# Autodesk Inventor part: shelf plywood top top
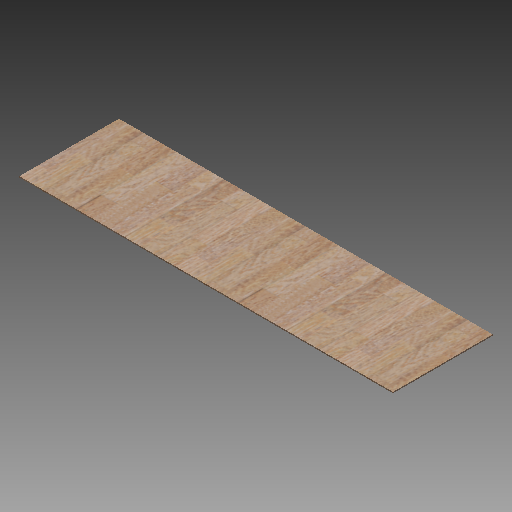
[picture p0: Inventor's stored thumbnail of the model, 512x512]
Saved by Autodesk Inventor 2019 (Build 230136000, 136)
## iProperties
Created: 2013-07
Part Number: shelf plywood top top
Material: Generic
Document SubType Name: Modeling
Designer: Patrick Rice
Density: 1 g/cm^3
Appearance: Red Oak - Natural
Author: Patrick Rice
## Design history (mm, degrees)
sketch "Sketch1"
  geometry: L1 (952.5, -254)-(-952.5, -254); L2 (-952.5, -254)-(-952.5, 254); L3 (-952.5, 254)-(952.5, 254); L4 (952.5, 254)-(952.5, -254); L5 (952.5, -254)-(-952.5, 254); L6 (-952.5, -254)-(952.5, 254); 1 further point
  constraints: 12 end point, 2 midpoint, 2 parallel, 1 horizontal, 1 perpendicular
  dimensions: "d0" = 1905 distance of L2.end L3.end; "d1" = 508 distance of L1.end L2.end
extrude "Extrusion1" new body sketch "Sketch1" distance "d2" = 6.35; taper "d3" = 0 deg
body "Solid1"
